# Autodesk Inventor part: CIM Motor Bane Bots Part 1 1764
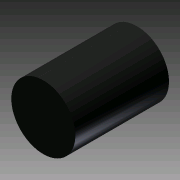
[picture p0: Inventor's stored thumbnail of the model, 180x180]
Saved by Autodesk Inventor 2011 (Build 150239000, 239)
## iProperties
Created: 2010-01
Part Number: CIM Motor Bane Bots Part 1 1764
Document SubType Name: Modeling
Designer: cmcfadden
Density: 1 g/cm^3
Author: cmcfadden
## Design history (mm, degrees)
sketch "Sketch1"
  geometry: C1 r 32.195 at (-6.759, -13.71); 1 further point
  constraints: 1 centre point
  dimensions: "d0" = 64.389 dimension on point (0, 0) C1.centre C1; "d0" = 64.389 diameter of C1
extrude "Extrusion1" new body sketch "Sketch1" distance "d1" = 94.234; taper "d2" = 0 deg
body "Solid1"
